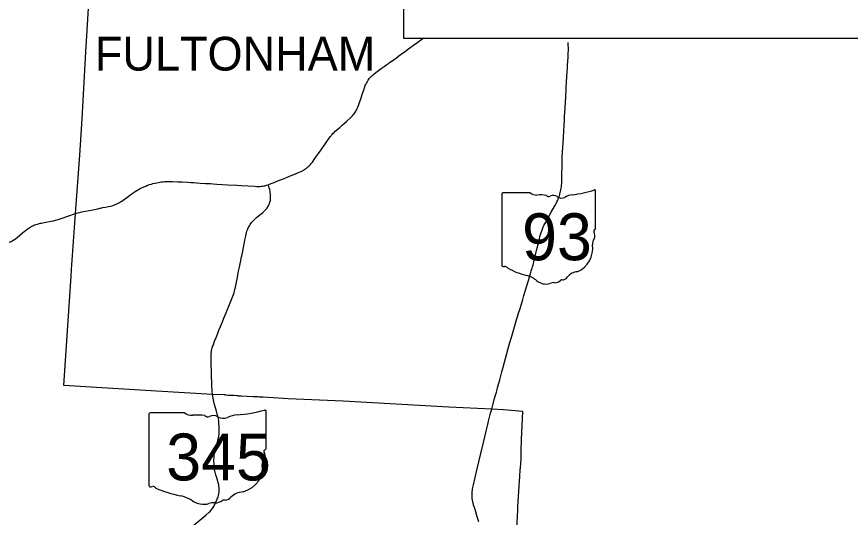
# Model space of a CAD drawing. Extents: x 1761803 to 2441803, y 509895 to 949895.
# Drawn here: x 2058370 to 2107842, y 750488 to 780187 of the extents above; entities that cross this region are included whole.
import ezdxf

# ---------------------------------------------------------------- set-up
doc = ezdxf.new("R2010")
doc.units = 0
for name, color, linetype in [('GM_X_County', 7, 'Continuous'), ('GM_X_County_Road', 7, 'Continuous'), ('GM_X_Minor_Lake', 7, 'Continuous'), ('GM_X_Minor_River_Text', 7, 'Continuous'), ('GM_X_State_Location', 7, 'Continuous'), ('GM_X_Township_Road', 7, 'Continuous')]:
    doc.layers.add(name, color=color, linetype=linetype)

msp = doc.modelspace()

# ---------------------------------------------------------------- linework, layer by layer
at = {"layer": 'GM_X_County'}
msp.add_lwpolyline([(2087469, 740337), (2088090, 750532), (2088118, 750906), (2088117, 751123), (2088195, 752342), (2088215, 752645), (2088227, 752862), (2088228, 752866), (2088232, 752943), (2088252, 753258), (2088258, 753338), (2088262, 753404), (2088268, 753485), (2088269, 753496), (2088279, 753613), (2088282, 753638), (2088306, 753992), (2088299, 754498), (2088300, 754555), (2088304, 754604), (2088311, 754687), (2088323, 754853), (2088337, 755112), (2088417, 756772), (2087258, 756871), (2086562, 756908), (2084011, 757023), (2077744, 757381), (2074475, 757526), (2072989, 757616), (2072960, 757615), (2072878, 757617), (2072769, 757623), (2072673, 757630), (2072517, 757635), (2072453, 757636), (2072409, 757634), (2071696, 757680), (2071561, 757685), (2071509, 757690), (2071432, 757696), (2071284, 757706), (2071103, 757714), (2070917, 757724), (2070819, 757727), (2070776, 757730), (2070752, 757734), (2070718, 757746), (2070708, 757753), (2069991, 757783), (2066671, 757979), (2061164, 758315), (2061595, 764788), (2061629, 765185), (2061867, 768511), (2062118, 771969), (2062252, 774134), (2062482, 778098), (2062557, 779379), (2062696, 781690)], dxfattribs=at)
at = {"layer": 'GM_X_Minor_Lake'}
for points in [[(2090963, 775559), (2090964, 775573), (2090973, 775737), (2090978, 775835), (2090988, 776015), (2090988, 776018), (2091006, 776310), (2091008, 776346), (2091025, 776608), (2091028, 776653), (2091042, 776877), (2091060, 777188), (2091066, 777293), (2091093, 777785), (2091099, 777895), (2091106, 778034), (2091107, 778044), (2091108, 778160), (2091108, 778334), (2091102, 778498), (2091098, 778655)], [(2090897, 774491), (2090901, 774549), (2090912, 774722), (2090924, 774918), (2090930, 775016), (2090940, 775180), (2090951, 775360), (2090956, 775458), (2090963, 775559)], [(2086908, 758179), (2086945, 758312), (2087035, 758645), (2087164, 759120), (2087242, 759404), (2087321, 759689), (2087440, 760132), (2087566, 760591), (2087640, 760860), (2087732, 761175), (2087753, 761243), (2088001, 762071), (2088157, 762589), (2088242, 762872), (2088401, 763406), (2088472, 763642), (2088570, 763972), (2088644, 764224), (2088801, 764742), (2088886, 765025), (2088910, 765103), (2088929, 765166), (2088957, 765260), (2088985, 765355), (2089013, 765449), (2089065, 765638), (2089106, 765797), (2089129, 765892), (2089267, 766483), (2089314, 766681), (2089387, 766995), (2089423, 767138), (2089459, 767264), (2089499, 767389), (2089531, 767482), (2089572, 767590), (2089623, 767711), (2089663, 767801), (2089707, 767889), (2089768, 768006), (2090094, 768594), (2090303, 768966), (2090382, 769110), (2090434, 769212), (2090475, 769301), (2090507, 769375), (2090514, 769391), (2090549, 769483), (2090576, 769560), (2090606, 769654), (2090632, 769749), (2090652, 769828), (2090669, 769908), (2090686, 770005), (2090699, 770102), (2090710, 770200), (2090717, 770298), (2090721, 770429), (2090726, 770757), (2090730, 770987), (2090733, 771137), (2090735, 771200), (2090739, 771725), (2090744, 771889), (2090755, 772118), (2090776, 772446), (2090792, 772691), (2090811, 773019), (2090832, 773412), (2090871, 774050), (2090888, 774333)], [(2090888, 774333), (2090895, 774460), (2090897, 774491)], [(2071714, 765932), (2071746, 766083), (2071829, 766499), (2071889, 766805), (2071912, 766933), (2071962, 767174), (2071987, 767286), (2072013, 767381), (2072037, 767459), (2072064, 767536), (2072088, 767597), (2072115, 767656), (2072145, 767715), (2072185, 767786), (2072227, 767856), (2072264, 767910), (2072314, 767975), (2072365, 768039), (2072420, 768100), (2072477, 768159), (2072536, 768215), (2072610, 768279), (2072699, 768352), (2072879, 768494), (2072968, 768568), (2073030, 768622), (2073078, 768667), (2073123, 768714), (2073167, 768764), (2073207, 768816), (2073245, 768869), (2073254, 768884), (2073272, 768911), (2073305, 768968), (2073335, 769026), (2073355, 769072), (2073372, 769118), (2073392, 769181), (2073409, 769244), (2073423, 769309), (2073431, 769358), (2073437, 769407), (2073440, 769456), (2073441, 769522), (2073438, 769588), (2073430, 769669), (2073419, 769751), (2073404, 769832), (2073386, 769912), (2073353, 770039), (2073311, 770185), (2073301, 770217)], [(2069991, 757783), (2069984, 757835), (2069976, 757917), (2069965, 758048), (2069954, 758244), (2069948, 758408), (2069942, 758588), (2069939, 758752), (2069938, 758818), (2069936, 758867), (2069934, 758982), (2069930, 759129), (2069918, 759556), (2069912, 759810), (2069909, 759966), (2069910, 760064), (2069913, 760130), (2069920, 760211), (2069931, 760309), (2069941, 760374), (2069956, 760454), (2069975, 760534), (2069996, 760610), (2069997, 760613), (2070022, 760690), (2070061, 760798), (2070114, 760936), (2070206, 761164), (2070281, 761347), (2070353, 761530), (2070390, 761621), (2070433, 761728), (2070457, 761788), (2070481, 761850), (2070518, 761941), (2070579, 762093), (2070667, 762305), (2070724, 762445), (2070796, 762625), (2070859, 762777), (2070951, 763005), (2071036, 763218), (2071191, 763598), (2071232, 763706), (2071268, 763815), (2071296, 763909), (2071320, 764005), (2071349, 764133), (2071414, 764438), (2071448, 764616), (2071499, 764873), (2071542, 765099), (2071588, 765324), (2071669, 765720), (2071714, 765932)], [(2086562, 756908), (2086647, 757221), (2086715, 757474), (2086785, 757727), (2086837, 757917), (2086879, 758075), (2086884, 758093), (2086908, 758179)], [(2068440, 749673), (2069593, 750613), (2069798, 750791), (2069852, 750842), (2069890, 750885), (2069953, 750964), (2069986, 751010), (2070025, 751071), (2070084, 751176), (2070248, 751519), (2070277, 751583), (2070300, 751637), (2070322, 751702), (2070349, 751786), (2070372, 751890), (2070388, 751998), (2070391, 752085), (2070391, 752152), (2070386, 752240), (2070375, 752340), (2070363, 752425), (2070335, 752533), (2070306, 752634), (2070229, 752882), (2070192, 753006), (2070169, 753087), (2070151, 753163), (2070134, 753237), (2070119, 753325), (2070104, 753431), (2070092, 753527), (2070083, 753655), (2070076, 753792), (2070079, 753916), (2070083, 754007), (2070088, 754075), (2070098, 754160), (2070112, 754267), (2070127, 754349), (2070146, 754455), (2070166, 754547), (2070215, 754715), (2070280, 754946), (2070309, 755048), (2070332, 755153), (2070357, 755276), (2070377, 755438), (2070382, 755511), (2070393, 755738), (2070392, 755878), (2070376, 756061), (2070358, 756212), (2070340, 756323), (2070322, 756409), (2070268, 756618), (2070219, 756785), (2070146, 757034), (2070106, 757183), (2070063, 757361), (2070026, 757553), (2069991, 757783)], [(2085470, 751264), (2085452, 751330), (2085432, 751414), (2085417, 751498), (2085402, 751612), (2085393, 751734), (2085391, 751821), (2085394, 751887), (2085399, 751966), (2085406, 752040), (2085415, 752103), (2085429, 752183), (2085445, 752262), (2085462, 752343), (2085480, 752418), (2085685, 753293), (2085913, 754268), (2086071, 754929), (2086249, 755684), (2086321, 755994), (2086370, 756195), (2086492, 756662), (2086562, 756908)], [(2085628, 750763), (2085531, 751063), (2085483, 751213), (2085470, 751264)], [(2085804, 750213), (2085723, 750464), (2085643, 750717), (2085628, 750763)]]:
    msp.add_lwpolyline(points, dxfattribs=at)
at = {"layer": 'GM_X_Minor_River_Text'}
for points in [[(2073301, 770217), (2073333, 770228), (2073470, 770282), (2073657, 770359), (2073691, 770373), (2073910, 770462), (2074138, 770554), (2074335, 770635), (2074564, 770726), (2074822, 770831), (2075096, 770942), (2075201, 770987), (2075290, 771030), (2075362, 771068), (2075419, 771100), (2075474, 771135), (2075541, 771182), (2075606, 771232), (2075656, 771274), (2075704, 771319), (2075751, 771365), (2075806, 771425), (2075859, 771488), (2075919, 771565), (2076063, 771765), (2076204, 771966), (2076336, 772154), (2076478, 772355), (2076609, 772543), (2076780, 772784), (2076922, 772985), (2076989, 773078), (2077004, 773097), (2077040, 773143), (2077083, 773193), (2077139, 773253), (2077208, 773323), (2077280, 773391), (2077538, 773619), (2077711, 773770), (2077809, 773858), (2077945, 773976), (2078007, 774030), (2078176, 774186), (2078246, 774254), (2078302, 774314), (2078355, 774376), (2078396, 774427), (2078434, 774480), (2078478, 774549), (2078519, 774620), (2078549, 774678), (2078577, 774737), (2078609, 774812), (2078651, 774919), (2078712, 775089), (2078786, 775306), (2078918, 775694), (2078982, 775880), (2079019, 775987), (2079025, 776004), (2079060, 776097), (2079093, 776172), (2079129, 776246), (2079160, 776304), (2079202, 776375), (2079238, 776430), (2079277, 776483), (2079317, 776535), (2079371, 776597), (2079427, 776657), (2079475, 776703), (2079524, 776746), (2079588, 776798), (2079757, 776928), (2080009, 777111), (2080182, 777236), (2080329, 777341), (2080450, 777428), (2080494, 777459), (2080541, 777495), (2080901, 777754), (2081153, 777937), (2081419, 778129), (2081565, 778235), (2081711, 778342), (2081924, 778494), (2082176, 778678), (2082415, 778851), (2082502, 778913)], [(2063312, 768822), (2063336, 768827), (2063481, 768858), (2063641, 768891), (2063818, 768927), (2063930, 768951), (2064010, 768971), (2064088, 768994), (2064166, 769020), (2064257, 769055), (2064317, 769081), (2064391, 769116), (2064463, 769154), (2064534, 769196), (2064603, 769240), (2064697, 769306), (2064961, 769501), (2065092, 769599), (2065197, 769678), (2065291, 769744), (2065400, 769817), (2065498, 769878), (2065575, 769924), (2065728, 770005), (2065801, 770041), (2065921, 770096), (2066027, 770141), (2066134, 770182), (2066258, 770226), (2066364, 770261), (2066404, 770273), (2066446, 770284), (2066574, 770316), (2066686, 770340), (2066783, 770358), (2066857, 770372), (2066940, 770385), (2067043, 770397), (2067141, 770406), (2067272, 770415), (2067387, 770419), (2067502, 770419), (2067580, 770417)], [(2067580, 770417), (2067617, 770416), (2067928, 770399), (2068190, 770383), (2068518, 770364), (2068698, 770351), (2068862, 770342), (2069255, 770318), (2069566, 770300), (2069778, 770287), (2069844, 770283), (2070024, 770271), (2070254, 770259), (2070581, 770240), (2070876, 770221), (2071432, 770188), (2071694, 770171), (2072495, 770123), (2072626, 770118), (2072724, 770117), (2072806, 770119), (2072888, 770125), (2072953, 770132), (2073033, 770145), (2073113, 770162), (2073193, 770182), (2073271, 770206), (2073301, 770217)], [(2061867, 768511), (2061922, 768527), (2062002, 768549), (2062108, 768573), (2062244, 768602), (2062446, 768644), (2062666, 768690), (2062881, 768734), (2063192, 768797), (2063312, 768822)], [(2060517, 768077), (2060555, 768085), (2060678, 768113), (2060759, 768131), (2060838, 768153), (2061013, 768205), (2061523, 768390), (2061752, 768473), (2061867, 768511)], [(2058739, 767379), (2058791, 767421), (2058866, 767483), (2058916, 767522), (2058976, 767568), (2059032, 767611), (2059113, 767667), (2059183, 767710), (2059234, 767738), (2059301, 767773), (2059363, 767801), (2059436, 767832), (2059499, 767856), (2059577, 767883), (2059658, 767904), (2059770, 767931), (2059847, 767947), (2059997, 767976), (2060420, 768057), (2060517, 768077)], [(2056787, 766746), (2057038, 766730), (2057167, 766722), (2057261, 766717), (2057347, 766712), (2057402, 766711), (2057472, 766712), (2057534, 766716), (2057615, 766726), (2057693, 766738), (2057766, 766755), (2057839, 766775), (2057915, 766801), (2057974, 766824), (2058044, 766856), (2058107, 766887), (2058193, 766942), (2058292, 767011), (2058390, 767089), (2058723, 767365), (2058739, 767379)]]:
    msp.add_lwpolyline(points, dxfattribs=at)
at = {"layer": 'GM_X_State_Location'}
msp.add_lwpolyline([(2081320, 778913), (2110696, 778913), (2110696, 793748), (2081320, 793748)], close=True, dxfattribs=at)
at = {"layer": 'GM_X_Township_Road'}
for p, q in [((2092729, 767632), (2092729, 769843)), ((2087160, 769666), (2087160, 765439)), ((2088846, 769739), (2087215, 769739)), ((2092728, 767633), (2092729, 767632)), ((2066214, 756604), (2066214, 752378)), ((2068321, 756677), (2066282, 756677)), ((2073174, 754571), (2073174, 756782)), ((2073174, 754571), (2073174, 754571))]:
    msp.add_line(p, q, dxfattribs=at)
for centre, radius, start, end in [((2090745, 775501), 5905, 275.8445, 288.9065), ((2092667, 769852), 62, 351.8621, 97.738), ((2087224, 769675), 64.5, 98.1301, 188.1301), ((2089234, 770229), 626, 231.6195, 271.1119), ((2089442, 767366), 2246, 80.4867, 94.9883), ((2089952, 769697), 181, 219.7921, 297.1024), ((2090217, 769208), 375, 54.4667, 119.1411), ((2090701, 769878), 452, 233.8562, 294.8282), ((2091499, 768448), 1188, 97.3462, 120.7689), ((2092715, 767470), 95.9, 107.944, 210.337), ((2092104, 767191), 576, 340.033, 23.6496), ((2092663, 767624), 66.3, 289.6038, 7.7341), ((2092951, 766707), 419, 136.8065, 186.9296), ((2091076, 766426), 1477, 292.3089, 8.9858), ((2087225, 765430), 65.1, 171.9584, 258.3066), ((2087235, 765862), 497, 267.339, 280.6039), ((2087336, 765195), 179, 29.7484, 93.2717), ((2089597, 768993), 4265, 240.4129, 257.1985), ((2091699, 764253), 809, 94.4031, 142.5768), ((2088326, 763541), 1334, 47.1842, 75.836), ((2089769, 765174), 847, 230.7004, 286.2918), ((2090258, 763713), 696, 85.6951, 111.2099), ((2090320, 764858), 451, 268.777, 315.5493), ((2090728, 764449), 127, 65.7517, 132.6484), ((2090674, 765030), 477, 282.8732, 323.2771)]:
    msp.add_arc(centre, radius, start, end, dxfattribs=at)
for centre, major_axis, start_param, end_param in [((2066293, 756613), (80.6, 0), 1.712693, 3.28349), ((2068806, 757168), (782, 0), 4.042523, 4.731795), ((2069066, 754304), (2808, 0), 1.404758, 1.657858), ((2069703, 756635), (226, 0), 3.836095, 5.185415), ((2070034, 756147), (469, 0), 0.950623, 2.079405), ((2070640, 756817), (564, 0), 4.081561, 5.145723), ((2071637, 755386), (1485, 0), 1.699011, 2.107814), ((2070695, 762439), (7382, 0), 4.814394, 5.042369), ((2073097, 756791), (77.5, 0), 6.141152, 7.989035), ((2073157, 754409), (120, 0), 1.883978, 3.671073), ((2073092, 754562), (82.9, 0), 5.05454, 6.418171), ((2072394, 754129), (720, 0), 5.934695, 6.695948), ((2071108, 753364), (1846, 0), 5.101752, 6.440018), ((2073452, 753646), (524, 0), 2.387724, 3.262537), ((2066294, 752369), (81.4, 0), 3.00124, 4.508301), ((2066306, 752801), (621, 0), 4.665946, 4.897461), ((2066434, 752134), (224, 0), 0.519207, 1.627899), ((2069260, 755931), (5331, 0), 4.195997, 4.488961), ((2071887, 751191), (1011, 0), 1.647645, 2.488434), ((2067671, 750479), (1668, 0), 0.823519, 1.323587), ((2070673, 751387), (159, 0), 1.147584, 2.315152), ((2070606, 751968), (597, 0), 4.937069, 5.64225), ((2069475, 752113), (1058, 0), 4.026481, 4.996735), ((2070086, 750652), (870, 0), 1.495662, 1.94098), ((2070163, 751797), (564, 0), 4.691044, 5.507374)]:
    msp.add_ellipse(centre, major_axis=major_axis, ratio=0.8, start_param=start_param, end_param=end_param, dxfattribs=at)

# ---------------------------------------------------------------- texts
at = {"layer": 'GM_X_County_Road'}
msp.add_text('FULTONHAM', height=2000, rotation=0, dxfattribs=at).set_placement((2063011, 776992))
at = {"layer": 'GM_X_Township_Road'}
for s, p in [('93', (2088362, 765737)), ('345', (2067243, 752676))]:
    msp.add_text(s, height=2784.4, dxfattribs=at).set_placement(p)

doc.saveas('drawing.dxf')
